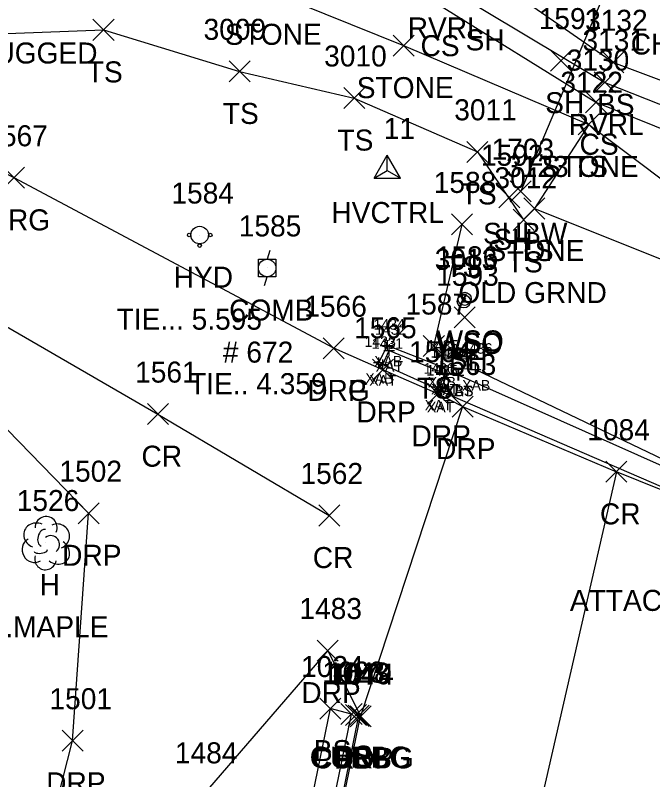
# Model space of a CAD drawing. Extents: x 462930 to 463548, y 29607 to 30453.
# Drawn here: x 463320.55 to 463339.03, y 30103.46 to 30125.62 of the extents above; entities that cross this region are included whole.
import ezdxf

# ---------------------------------------------------------------- set-up
doc = ezdxf.new("R2010")
doc.units = 0
for name, color, linetype in [('B_A', 7, 'Continuous'), ('B_I', 7, 'Continuous'), ('B_TIC', 7, 'Continuous'), ('BSE', 7, 'Continuous'), ('BSUBM', 7, 'Continuous'), ('C_A', 7, 'Continuous'), ('C_I', 7, 'Continuous'), ('CPSM', 7, 'Continuous'), ('D_C', 7, 'Continuous'), ('L_A', 7, 'Continuous'), ('L_C', 7, 'Continuous'), ('L_I', 7, 'Continuous'), ('L_TIC', 7, 'Continuous'), ('LASF', 7, 'Continuous'), ('LAWE', 7, 'Continuous'), ('LELB', 7, 'Continuous'), ('LTD', 7, 'Continuous'), ('P_A', 7, 'Continuous'), ('P_I', 7, 'Continuous'), ('P_TIC', 7, 'Continuous'), ('PET', 7, 'Continuous'), ('PRC', 7, 'Continuous'), ('R_A', 7, 'Continuous'), ('R_I', 7, 'Continuous'), ('R_TIC', 7, 'Continuous'), ('RC', 7, 'Continuous'), ('RDG', 7, 'Continuous'), ('RDP', 7, 'Continuous'), ('U_A', 7, 'Continuous'), ('U_C', 7, 'Continuous'), ('U_I', 7, 'Continuous'), ('U_TIC', 7, 'Continuous'), ('UP', 7, 'Continuous'), ('UW', 7, 'Continuous'), ('UWFH', 7, 'Continuous'), ('UWV', 7, 'Continuous')]:
    doc.layers.add(name, color=color, linetype=linetype)

msp = doc.modelspace()

# ---------------------------------------------------------------- linework, layer by layer
at = {"layer": 'B_TIC'}
for p, q in [((463331.348, 30116.049), (463331.371, 30116.049)), ((463331.393, 30115.9), (463331.416, 30115.9)), ((463331.089, 30115.549), (463331.112, 30115.549)), ((463331.211, 30115.493), (463331.234, 30115.493)), ((463332.901, 30115.442), (463332.924, 30115.442)), ((463333.001, 30115.238), (463333.024, 30115.238)), ((463333.068, 30115.223), (463333.091, 30115.223)), ((463333.396, 30115.186), (463333.419, 30115.186)), ((463333.396, 30115.186), (463333.419, 30115.186)), ((463333.406, 30115.185), (463333.429, 30115.185)), ((463333.897, 30115.351), (463333.92, 30115.351)), ((463332.815, 30114.773), (463332.838, 30114.773)), ((463332.881, 30114.719), (463332.904, 30114.719))]:
    msp.add_line(p, q, dxfattribs=at)
for points in [[(463331.195, 30116.049), (463331.499, 30116.049)], [(463331.347, 30115.897), (463331.347, 30116.201)], [(463331.392, 30115.748), (463331.392, 30116.052)], [(463331.24, 30115.9), (463331.544, 30115.9)], [(463331.088, 30115.397), (463331.088, 30115.701)], [(463331.21, 30115.341), (463331.21, 30115.645)], [(463332.9, 30115.29), (463332.9, 30115.594)], [(463330.936, 30115.549), (463331.24, 30115.549)], [(463331.058, 30115.493), (463331.362, 30115.493)], [(463332.748, 30115.442), (463333.052, 30115.442)], [(463333, 30115.086), (463333, 30115.39)], [(463333.067, 30115.071), (463333.067, 30115.375)], [(463333.896, 30115.199), (463333.896, 30115.503)], [(463332.848, 30115.238), (463333.152, 30115.238)], [(463332.915, 30115.223), (463333.219, 30115.223)], [(463333.243, 30115.186), (463333.547, 30115.186)], [(463333.243, 30115.186), (463333.547, 30115.186)], [(463333.253, 30115.185), (463333.557, 30115.185)], [(463333.395, 30115.034), (463333.395, 30115.338)], [(463333.395, 30115.034), (463333.395, 30115.338)], [(463333.405, 30115.033), (463333.405, 30115.337)], [(463333.744, 30115.351), (463334.048, 30115.351)], [(463332.814, 30114.621), (463332.814, 30114.925)], [(463332.662, 30114.773), (463332.966, 30114.773)], [(463332.728, 30114.719), (463333.032, 30114.719)], [(463332.88, 30114.567), (463332.88, 30114.871)]]:
    msp.add_lwpolyline(points, dxfattribs=at)
at = {"layer": 'BSE'}
for points in [[(463333.395, 30115.186), (463333.405, 30115.185)], [(463333.405, 30115.185), (463343.765, 30110.566)]]:
    msp.add_lwpolyline(points, dxfattribs=at)
at = {"layer": 'BSUBM'}
for points in [[(463331.088, 30115.549), (463331.347, 30116.049), (463332.9, 30115.442), (463333.896, 30115.351), (463342.287, 30111.327), (463344.216, 30110.532), (463343.954, 30109.898), (463342.919, 30107.626)], [(463333, 30115.238), (463332.814, 30114.773), (463331.21, 30115.493), (463331.392, 30115.9)], [(463331.392, 30115.9), (463333, 30115.238)], [(463343.764, 30110.564), (463344.011, 30110.471), (463343.819, 30109.984), (463332.88, 30114.719), (463333.067, 30115.223), (463333.395, 30115.186)]]:
    msp.add_lwpolyline(points, dxfattribs=at)
at = {"layer": 'CPSM'}
for p, q in [((463330.953, 30120.9), (463331.334, 30121.56)), ((463331.715, 30120.9), (463331.334, 30121.56)), ((463331.334, 30121.12), (463331.334, 30121.56)), ((463330.953, 30120.9), (463331.334, 30121.12)), ((463330.953, 30120.9), (463331.715, 30120.9)), ((463331.334, 30121.12), (463331.334, 30121.12)), ((463331.334, 30121.12), (463331.715, 30120.9))]:
    msp.add_line(p, q, dxfattribs=at)
at = {"layer": 'L_TIC'}
for points in [[(463322.806, 30124.891), (463323.416, 30125.501)], [(463323.416, 30124.891), (463322.806, 30125.501)], [(463331.505, 30124.435), (463332.115, 30125.045)], [(463332.115, 30124.435), (463331.505, 30125.045)], [(463336.068, 30123.998), (463336.678, 30124.608)], [(463336.678, 30123.998), (463336.068, 30124.608)], [(463337.585, 30123.949), (463338.195, 30124.558)], [(463338.195, 30123.949), (463337.585, 30124.558)], [(463326.75, 30123.687), (463327.359, 30124.296)], [(463327.359, 30123.687), (463326.75, 30124.296)], [(463337.336, 30123.37), (463337.946, 30123.979)], [(463337.946, 30123.37), (463337.336, 30123.979)], [(463330.072, 30122.915), (463330.682, 30123.524)], [(463330.682, 30122.915), (463330.072, 30123.524)], [(463337.079, 30122.795), (463337.688, 30123.405)], [(463337.688, 30122.795), (463337.079, 30123.405)], [(463336.869, 30122.152), (463337.479, 30122.762)], [(463337.479, 30122.152), (463336.869, 30122.762)], [(463336.869, 30122.152), (463337.479, 30122.762)], [(463337.479, 30122.152), (463336.869, 30122.762)], [(463333.644, 30121.355), (463334.253, 30121.964)], [(463334.253, 30121.355), (463333.644, 30121.964)], [(463334.568, 30120.037), (463335.178, 30120.647)], [(463335.178, 30120.037), (463334.568, 30120.647)], [(463335.294, 30119.713), (463335.904, 30120.323)], [(463335.904, 30119.713), (463335.294, 30120.323)], [(463335.294, 30119.713), (463335.904, 30120.323)], [(463335.904, 30119.713), (463335.294, 30120.323)], [(463333.198, 30119.25), (463333.808, 30119.86)], [(463333.808, 30119.25), (463333.198, 30119.86)], [(463334.982, 30119.384), (463335.592, 30119.994)], [(463335.592, 30119.384), (463334.982, 30119.994)], [(463333.27, 30116.558), (463333.88, 30117.168)], [(463333.88, 30116.558), (463333.27, 30117.168)], [(463332.38, 30115.724), (463332.99, 30116.334)], [(463332.99, 30115.724), (463332.38, 30116.334)], [(463329.377, 30105.217), (463329.987, 30105.827)], [(463329.987, 30105.217), (463329.377, 30105.827)], [(463329.994, 30105.056), (463330.604, 30105.666)], [(463330.604, 30105.056), (463329.994, 30105.666)]]:
    msp.add_lwpolyline(points, dxfattribs=at)
at = {"layer": 'LASF'}
msp.add_lwpolyline([(463302.508, 30136.744), (463309.807, 30134.07), (463314.097, 30132.787), (463314.835, 30129.355), (463318.543, 30127.958), (463323.464, 30127.612), (463327.985, 30126.286), (463331.81, 30124.74), (463337.174, 30122.457), (463335.599, 30120.018), (463340.457, 30118.077), (463343.625, 30116.989)], dxfattribs=at)
at = {"layer": 'LAWE'}
msp.add_lwpolyline([(463303.761, 30138.951), (463311.513, 30136.497), (463315.004, 30134.116), (463316.958, 30131.951), (463319.339, 30130.596), (463324.938, 30129.932), (463327.547, 30128.313), (463332.975, 30126.47), (463337.641, 30123.674), (463341.966, 30121.958), (463344.49, 30119.626), (463346.795, 30118.444), (463349.584, 30118.528), (463352.681, 30116.677), (463355.961, 30113.875), (463359.993, 30113.221), (463365.135, 30110.482), (463368.778, 30108.638), (463372.593, 30105.432)], dxfattribs=at)
at = {"layer": 'LELB'}
for points in [[(463303.951, 30140.018), (463311.358, 30137.763), (463317.49, 30134.193), (463325.042, 30130.081), (463328.062, 30128.844), (463333.248, 30127.486), (463337.89, 30124.253), (463342.916, 30122.365), (463345.021, 30120.043), (463346.984, 30119.167), (463349.819, 30119.192), (463353.514, 30117.826), (463357.518, 30115.65), (463360.726, 30114.785), (463365.845, 30111.76), (463369.152, 30109.504), (463372.544, 30107.449)], [(463303.076, 30138.323), (463311.018, 30135.245), (463314.543, 30133.39), (463316.477, 30129.737), (463318.725, 30129.305), (463323.995, 30128.426), (463327.48, 30127.705), (463332.775, 30125.956), (463337.384, 30123.1), (463341.878, 30121.285), (463344.206, 30119.085), (463346.364, 30117.777), (463348.209, 30116.851), (463350.137, 30117.27)], [(463301.721, 30133.704), (463306.512, 30132.164), (463311.896, 30130.72), (463311.966, 30128.116), (463314.539, 30126.334), (463317.557, 30125.13), (463319.544, 30125.058), (463323.111, 30125.196), (463327.055, 30123.992), (463330.377, 30123.22), (463333.948, 30121.659), (463335.287, 30119.689), (463335.599, 30120.018)], [(463337.174, 30122.457), (463340.747, 30119.773), (463343.306, 30118.195), (463343.625, 30116.989)], [(463332.685, 30116.029), (463333.503, 30119.555)], [(463338.373, 30022.22), (463340.767, 30011.24), (463345.965, 29995.767), (463346.937, 29987.36), (463347.521, 29987.525), (463346.646, 29996.093), (463342.063, 30011.435), (463339.344, 30022.565), (463336.301, 30037.573), (463333.414, 30053.384), (463330.633, 30068.275), (463328.629, 30079.728), (463328.086, 30089.487), (463328.627, 30097.184), (463330.299, 30105.361), (463329.682, 30105.522), (463327.994, 30097.289)]]:
    msp.add_lwpolyline(points, dxfattribs=at)
at = {"layer": 'LTD'}
msp.add_line((463321.434, 30110.333), (463321.434, 30110.333), dxfattribs=at)
msp.add_line((463321.434, 30110.333), (463321.434, 30110.333), dxfattribs=at)
msp.add_arc((463321.448, 30110.77), 0.319, 335.5272, 180.9563, dxfattribs=at)
for centre, major_axis, ratio, start_param, end_param in [((463321.193, 30110.536), (0.369, -0.156), 0.895232, 1.570796, 4.712389), ((463321.37, 30110.473), (-0.063, -0.241), 0.645439, 3.141593, 6.283185), ((463321.751, 30110.511), (-0.348, -0.147), 0.949671, 1.570796, 4.712389), ((463321.586, 30110.282), (-0.152, 0.203), 0.989748, 3.141593, 6.283185), ((463321.104, 30110.117), (0.178, -0.317), 0.959034, 3.141593, 6.283185), ((463321.739, 30110.079), (-0.332, 0.241), 0.841452, 1.570796, 4.712389), ((463321.294, 30110.104), (-0.19, -0.025), 0.423636, 0, 3.141593), ((463321.434, 30109.876), (0.081, 0.323), 0.942809, 1.570796, 4.712389)]:
    msp.add_ellipse(centre, major_axis=major_axis, ratio=ratio, start_param=start_param, end_param=end_param, dxfattribs=at)
at = {"layer": 'P_TIC'}
for points in [[(463324.384, 30113.752), (463324.994, 30114.362)], [(463324.994, 30113.752), (463324.384, 30114.362)], [(463337.673, 30112.08), (463338.283, 30112.69)], [(463338.283, 30112.08), (463337.673, 30112.69)], [(463329.35, 30110.813), (463329.96, 30111.423)], [(463329.96, 30110.813), (463329.35, 30111.423)], [(463330.256, 30104.995), (463330.866, 30105.605)], [(463330.866, 30104.995), (463330.256, 30105.605)]]:
    msp.add_lwpolyline(points, dxfattribs=at)
at = {"layer": 'PET'}
for points in [[(463341.961, 30110.783), (463337.978, 30112.385)], [(463349.052, 29990.82), (463346.99, 29996.409), (463342.314, 30011.546), (463339.633, 30022.646), (463336.631, 30037.644), (463333.669, 30053.397), (463330.887, 30068.339), (463328.89, 30079.76), (463328.357, 30089.522), (463328.892, 30097.183), (463330.561, 30105.3)]]:
    msp.add_lwpolyline(points, dxfattribs=at)
at = {"layer": 'PRC'}
for points in [[(463295.271, 30125.464), (463304.437, 30123.104), (463315.967, 30119.096), (463324.689, 30114.057), (463329.655, 30111.118)], [(463337.978, 30112.385), (463335.087, 30099.771), (463333.576, 30084.385), (463334.686, 30068.796), (463337.03, 30053.748), (463339.908, 30038.01), (463343.632, 30023.045), (463346.617, 30012.904), (463351.044, 29997.524), (463354.76, 29987.177), (463360.584, 29974.202), (463367.548, 29960.534), (463374.695, 29948.349)]]:
    msp.add_lwpolyline(points, dxfattribs=at)
at = {"layer": 'R_TIC'}
for points in [[(463320.214, 30120.602), (463320.824, 30121.212)], [(463320.824, 30120.602), (463320.214, 30121.212)], [(463329.477, 30115.66), (463330.087, 30116.27)], [(463330.087, 30115.66), (463329.477, 30116.27)], [(463329.477, 30115.66), (463330.087, 30116.27)], [(463330.087, 30115.66), (463329.477, 30116.27)], [(463330.904, 30115.037), (463331.514, 30115.647)], [(463331.514, 30115.037), (463330.904, 30115.647)], [(463332.498, 30114.343), (463333.108, 30114.953)], [(463333.108, 30114.343), (463332.498, 30114.953)], [(463333.212, 30113.971), (463333.822, 30114.581)], [(463333.822, 30113.971), (463333.212, 30114.581)], [(463322.373, 30110.879), (463322.983, 30111.489)], [(463322.983, 30110.879), (463322.373, 30111.489)], [(463329.305, 30106.898), (463329.915, 30107.508)], [(463329.915, 30106.898), (463329.305, 30107.508)], [(463330.128, 30105.03), (463330.738, 30105.64)], [(463330.738, 30105.03), (463330.128, 30105.64)], [(463330.201, 30105.006), (463330.811, 30105.616)], [(463330.811, 30105.006), (463330.201, 30105.616)], [(463321.911, 30104.284), (463322.521, 30104.894)], [(463322.521, 30104.284), (463321.911, 30104.894)]]:
    msp.add_lwpolyline(points, dxfattribs=at)
at = {"layer": 'RC'}
msp.add_lwpolyline([(463330.433, 30105.335), (463330.506, 30105.311), (463328.851, 30097.179), (463328.319, 30089.513), (463328.85, 30079.744), (463330.845, 30068.328), (463333.629, 30053.397), (463336.583, 30037.649), (463339.548, 30022.613), (463342.224, 30011.501), (463346.871, 29996.398), (463346.791, 29996.353)], dxfattribs=at)
at = {"layer": 'RDG'}
msp.add_lwpolyline([(463329.782, 30115.965), (463320.519, 30120.907), (463309.444, 30126.512), (463298.751, 30131.137)], dxfattribs=at)
at = {"layer": 'RDP'}
for points in [[(463319.513, 30094.018), (463322.216, 30104.589), (463322.678, 30111.184), (463317.965, 30116.023), (463310.345, 30118.227), (463299.708, 30118.434), (463291.709, 30117.924)], [(463333.517, 30114.276), (463332.803, 30114.648), (463331.209, 30115.342), (463329.782, 30115.965)], [(463333.517, 30114.276), (463330.561, 30105.3)], [(463333.517, 30114.276), (463337.978, 30112.385)], [(463329.61, 30107.203), (463326.001, 30103.02), (463321.75, 30087.148), (463322.748, 30078.455), (463323.504, 30066.246), (463318.638, 30068.319), (463319.452, 30074.807), (463317.191, 30075.893), (463318.57, 30082.354), (463317.087, 30083.2)], [(463329.61, 30107.203), (463330.561, 30105.3)]]:
    msp.add_lwpolyline(points, dxfattribs=at)
at = {"layer": 'U_TIC'}
for points in [[(463334.9, 30120.212), (463335.51, 30120.822)], [(463335.51, 30120.212), (463334.9, 30120.822)]]:
    msp.add_lwpolyline(points, dxfattribs=at)
at = {"layer": 'UP'}
for p, q in [((463327.929, 30118.801), (463327.853, 30118.547)), ((463327.599, 30118.039), (463327.599, 30118.547)), ((463327.599, 30118.547), (463328.107, 30118.547)), ((463328.107, 30118.547), (463328.107, 30118.039)), ((463327.853, 30118.293), (463327.853, 30118.293)), ((463328.107, 30118.039), (463327.599, 30118.039)), ((463327.777, 30117.785), (463327.853, 30118.039))]:
    msp.add_line(p, q, dxfattribs=at)
msp.add_circle((463327.853, 30118.293), 0.254, dxfattribs=at)
at = {"layer": 'UW'}
msp.add_lwpolyline([(463346.016, 30146.118), (463335.205, 30120.517)], dxfattribs=at)
at = {"layer": 'UWFH'}
msp.add_line((463325.9, 30119.247), (463325.9, 30119.247), dxfattribs=at)
for centre, radius in [((463325.9, 30119.247), 0.254), ((463325.595, 30119.247), 0.0508), ((463326.205, 30119.247), 0.0508), ((463325.9, 30118.942), 0.0508)]:
    msp.add_circle(centre, radius, dxfattribs=at)
at = {"layer": 'UWV'}
for centre, radius in [((463333.579, 30117.398), 0.191), ((463333.556, 30117.325), 0.191), ((463333.579, 30117.398), 0.0254), ((463333.556, 30117.325), 0.0254)]:
    msp.add_circle(centre, radius, dxfattribs=at)

# ---------------------------------------------------------------- texts
at = {"layer": 'B_A'}
for s, p in [('XAB', (463330.957, 30115.439)), ('XAT', (463330.997, 30115.29)), ('XAB', (463330.698, 30114.939)), ('XAT', (463330.815, 30114.883)), ('XAB', (463332.51, 30114.832)), ('XAT', (463332.605, 30114.628)), ('XAT', (463332.672, 30114.613)), ('XAB', (463333.506, 30114.741)), ('XAT', (463333, 30114.576)), ('XBS', (463333.011, 30114.576)), ('XBS', (463333.021, 30114.575)), ('XAT', (463332.419, 30114.163)), ('XAT', (463332.485, 30114.109))]:
    msp.add_text(s, height=0.3048, dxfattribs=at).set_placement(p)
at = {"layer": 'B_I'}
for s, p in [('1434', (463330.937, 30116.506)), ('1432', (463330.982, 30116.357)), ('1433', (463330.678, 30116.006)), ('1431', (463330.886, 30115.95)), ('1435', (463332.49, 30115.899)), ('1436', (463333.477, 30115.808)), ('1429', (463332.588, 30115.695)), ('1426', (463332.648, 30115.68)), ('1427', (463332.985, 30115.643)), ('1427', (463332.985, 30115.643)), ('1428', (463332.995, 30115.642)), ('1430', (463332.39, 30115.23)), ('1425', (463332.47, 30115.176))]:
    msp.add_text(s, height=0.3048, dxfattribs=at).set_placement(p)
at = {"layer": 'C_A'}
msp.add_text('HVCTRL', height=0.6096, dxfattribs=at).set_placement((463329.716, 30119.596))
at = {"layer": 'C_I'}
msp.add_text('11', height=0.6096, dxfattribs=at).set_placement((463331.233, 30122.034))
at = {"layer": 'D_C'}
msp.add_text('.305 CPEP-NEW-PLUGGED', height=0.6096, dxfattribs=at).set_placement((463312.474, 30124.22))
at = {"layer": 'L_A'}
for s, height, p in [('RVRL', 0.6096, (463331.928, 30124.946)), ('STONE', 0.6096, (463326.627, 30124.762)), ('SH', 0.6096, (463333.605, 30124.6)), ('CS', 0.6096, (463332.3, 30124.432)), ('CH', 0.6096, (463338.392, 30124.48)), ('TS', 0.6096, (463322.626, 30123.672)), ('STONE', 0.6096, (463330.451, 30123.216)), ('SH', 0.6096, (463335.912, 30122.779)), ('BS', 0.6096, (463337.415, 30122.729)), ('TS', 0.6096, (463326.57, 30122.468)), ('RVRL', 0.6096, (463336.595, 30122.15)), ('TS', 0.6096, (463329.892, 30121.696)), ('CS', 0.6096, (463336.908, 30121.576)), ('STONE', 0.6096, (463335.815, 30120.933)), ('TS', 0.6096, (463336.689, 30120.933)), ('TS', 0.6096, (463333.464, 30120.135)), ('SH', 0.6096, (463334.412, 30118.818)), ('STONE', 0.6096, (463334.24, 30118.494)), ('TS', 0.6096, (463335.114, 30118.494)), ('TS', 0.6096, (463334.802, 30118.165)), ('TS', 0.6096, (463333.018, 30118.031)), ('SH', 0.6096, (463333.114, 30115.339)), ('TS', 0.6096, (463332.2, 30114.505)), ('H', 0.61, (463321.261, 30108.809)), ('BS', 0.6096, (463329.207, 30103.998)), ('BS', 0.6096, (463329.824, 30103.837))]:
    msp.add_text(s, height=height, dxfattribs=at).set_placement(p)
at = {"layer": 'L_C'}
for s, p in [('OLD GRND', (463333.398, 30117.275)), ('M.MAPLE', (463319.586, 30107.59))]:
    msp.add_text(s, height=0.6096, dxfattribs=at).set_placement(p)
at = {"layer": 'L_I'}
for s, p in [('1591', (463335.725, 30125.217)), ('3132', (463337.069, 30125.168)), ('3009', (463326.011, 30124.906)), ('3131', (463336.993, 30124.589)), ('3010', (463329.506, 30124.134)), ('3130', (463336.536, 30124.015)), ('3122', (463336.353, 30123.372)), ('3122', (463336.353, 30123.372)), ('3011', (463333.277, 30122.574)), ('1592', (463334.052, 30121.256)), ('3123', (463334.778, 30120.932)), ('3123', (463334.778, 30120.932)), ('3012', (463334.442, 30120.603)), ('1588', (463332.682, 30120.469)), ('1593', (463332.754, 30117.777)), ('1587', (463331.864, 30116.943)), ('1526', (463320.596, 30111.247)), ('1024', (463328.837, 30106.436)), ('1023', (463329.454, 30106.275))]:
    msp.add_text(s, height=0.6096, dxfattribs=at).set_placement(p)
at = {"layer": 'P_A'}
for s, p in [('CR', (463324.211, 30112.533)), ('CR', (463337.5, 30110.861)), ('CR', (463329.177, 30109.594)), ('RDP', (463329.795, 30103.776))]:
    msp.add_text(s, height=0.6096, dxfattribs=at).set_placement(p)
at = {"layer": 'P_I'}
for s, p in [('1561', (463324.027, 30114.971)), ('1084', (463337.133, 30113.299)), ('1562', (463328.82, 30112.032)), ('1074', (463329.716, 30106.214))]:
    msp.add_text(s, height=0.6096, dxfattribs=at).set_placement(p)
at = {"layer": 'R_A'}
for s, p in [('DRG', (463319.753, 30119.383)), ('DRG', (463329.016, 30114.441)), ('DRP', (463329.016, 30114.441)), ('DRP', (463330.443, 30113.818)), ('DRP', (463332.037, 30113.124)), ('DRP', (463332.751, 30112.752)), ('DRP', (463321.912, 30109.66)), ('DRP', (463328.844, 30105.679)), ('CURBG', (463329.087, 30103.811)), ('CURBG', (463329.16, 30103.787)), ('DRP', (463321.45, 30103.065))]:
    msp.add_text(s, height=0.6096, dxfattribs=at).set_placement(p)
at = {"layer": 'R_I'}
for s, p in [('1567', (463319.684, 30121.821)), ('1566', (463328.93, 30116.879)), ('1566', (463328.93, 30116.879)), ('1565', (463330.374, 30116.256)), ('1564', (463331.968, 30115.562)), ('1563', (463332.682, 30115.19)), ('1502', (463321.833, 30112.098)), ('1483', (463328.789, 30108.117)), ('1048', (463329.588, 30106.249)), ('1049', (463329.659, 30106.225)), ('1501', (463321.544, 30105.503)), ('1484', (463325.18, 30103.934))]:
    msp.add_text(s, height=0.6096, dxfattribs=at).set_placement(p)
at = {"layer": 'U_A'}
for s, p in [('SUBW', (463334.111, 30118.993)), ('HYD', (463325.144, 30117.723)), ('COMB', (463326.751, 30116.769)), ('WSO', (463332.765, 30115.874)), ('WSO', (463332.742, 30115.801))]:
    msp.add_text(s, height=0.6096, dxfattribs=at).set_placement(p)
at = {"layer": 'U_C'}
for s, p in [('TIE... 5.595', (463323.491, 30116.504)), ('# 672', (463326.571, 30115.55)), ('TIE.. 4.359', (463325.59, 30114.635)), ('ATTACHED TO BRIDGE, NOT IN USE', (463336.629, 30108.353))]:
    msp.add_text(s, height=0.6096, dxfattribs=at).set_placement(p)
at = {"layer": 'U_I'}
for s, p in [('1703', (463334.36, 30121.431)), ('1584', (463325.079, 30120.161)), ('1585', (463327.032, 30119.207)), ('1586', (463332.741, 30118.312)), ('3013', (463332.711, 30118.239))]:
    msp.add_text(s, height=0.6096, dxfattribs=at).set_placement(p)

doc.saveas('drawing.dxf')
